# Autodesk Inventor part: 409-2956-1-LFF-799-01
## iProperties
Created: 2010-11
Part Number: 409-2956-1-LFF-799-01
Material: 3/4" OD TUBE - SS
Document SubType Name: Modeling
Designer: S. Boerckel
Engineer: Steve Boerckel
Mass: 55.5632 g
Surface Area: 85.1076 cm^2
Volume: 6.87664 cm^3
Density: 8.08 g/cm^3
Description: DRAIN TUBING
Length: 3.000 in
Author: S. Boerckel
Revision Number: 0
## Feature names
1. Extrusion1
